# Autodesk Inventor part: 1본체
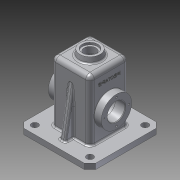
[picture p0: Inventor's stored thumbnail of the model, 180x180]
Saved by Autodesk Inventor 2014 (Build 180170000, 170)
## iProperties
Created: 2016-02
Part Number: 1본체
Material: 알루미늄 6061
Document SubType Name: Modeling
Designer: SEC
Density: 2.71 g/cm^3
Appearance: 알루미늄 - 평지
Mass: 923.206 g
Surface Area: 1053.79 cm^2
Volume: 340.666 cm^3
Author: SEC
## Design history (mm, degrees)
sketch "스케치1"
  geometry: L1 (-35, 60)-(35, 60); L2 (35, 60)-(35, -60); L3 (35, -60)-(-35, -60); L4 (-35, -60)-(-35, 60); L5 (-35, 60)-(35, -60); L6 (35, 60)-(-35, -60); 1 further point
  constraints: 12 end point, 2 midpoint, 2 parallel, 1 horizontal, 1 perpendicular
  dimensions: "d0" = 70 distance of L1.start L1.end; "d1" = 120 distance of L1.end L2.end
extrude "돌출1" new body sketch "스케치1" stored distance "d2" = 70; taper "d3" = 0 deg
sketch "스케치2"
  geometry: L1 (-35, -60)-(35, -60) reference; C1 r 27.5 at (0, -5); 1 further point
  constraints: 1 centre point, 1 vertical alignment
  dimensions: "d4" = 55 diameter of C1; "d5" = 55 distance from line of C1.centre L1
extrude "돌출2" join sketch "스케치2" distance "d6" = 13; taper "d7" = 0 deg
sketch "스케치3"
  geometry: L1 (22.5, 48)-(-32.5, 48) reference; L2 (22.5, -48)-(-32.5, -48) reference; L3 (-60, 35)-(-60, -35) reference; L4 (60, -35)-(60, 35) reference; L5 (-5, 48)-(-5, -48); L6 (55, 30)-(55, -30); L7 (60, 35)-(-60, 35) reference; L8 (-60, -35)-(60, -35) reference; L9 (-60, 30)-(-60, -30); L10 (55, 30)-(-60, 30); L11 (55, -30)-(-60, -30); 1 further point
  constraints: 10 end point, 2 midpoint, 2 point on line, 1 collinear, 1 parallel, 1 perpendicular
  dimensions: "d13" = 5 distance between parallel lines of L6 L4; "d35" = 5 distance between parallel lines of L7 L10; "d36" = 5 distance between parallel lines of L8 L11
extrude "돌출3" cut sketch "스케치3" stored distance "d19" = 60; taper "d20" = 0 deg
fillet "모깎기3" dims "d23" = 8
fillet "모깎기4" dims "d24" = 8
sketch "스케치4"
  geometry: L1 (22.5, 48)-(-32.5, 48) reference; L2 (22.5, -48)-(-32.5, -48) reference; L3 (-60, 27)-(-60, 35) reference; L4 (-60, -30)-(-60, 30) reference; L5 (-60, -35)-(-60, -27) reference; L6 (-5, 48)-(-5, -48); L7 (-60, 30)-(55, 30) reference; L8 (22.5, 30)-(15.5, 23); L9 (15.5, 23)-(12.5, 23); L10 (12.5, 23)-(12.5, 30); L11 (22.5, 30)-(12.5, 30); 1 further point
  constraints: 10 end point, 2 midpoint, 2 point on line, 1 collinear, 1 parallel, 1 perpendicular
  dimensions: "d37" = 55 diameter of L8.start L6; "d38" = 7 distance from line of L7 L8.end; "d39" = 135 deg angle of L7 L8; "d40" = 35 diameter of L9.end L6
revolve "회전1" sketch "스케치4" stored, may be unused: angle "d41" = 90 deg
hole "구멍1" diameter "d27" = 32; stored, may be unused: countersink angle "d31" = 90 deg, drill point angle "d33" = 118 deg; dims "d25" = 10, "d26" = 10, "d28" = 6, "d29" = 4, "d30" = 2, "d32" = 8
node "작업 평면1"
sketch "스케치5"
  geometry: C1 r 20 at (27, 27); 1 further point
  constraints: 1 centre point, 1 coincident
  dimensions: "d43" = 40 diameter of C1
extrude "돌출4" join sketch "스케치5" stored distance "d44" = 60; taper "d45" = 0 deg
sketch "스케치6"
  geometry: L1 (60, 27)-(60, -27) reference; L2 (70, 20)-(60, 20) reference; L3 (70, -20)-(60, -20) reference; L4 (70, 0)-(0, 0); L5 (60, 20)-(70, 20); L6 (60, 20)-(70, 18.237); L7 (70, 20)-(70, 18.237); L8 (0.22, 35)-(52, 35) reference
  constraints: 8 end point, 1 collinear, 1 parallel, 1 perpendicular
  dimensions: "d46" = 10 deg angle of L8 L6
revolve "회전2" sketch "스케치6" stored, may be unused: angle "d47" = 90 deg
hole "구멍2" diameter "d50" = 21; stored, may be unused: countersink angle "d54" = 90 deg, drill point angle "d56" = 118 deg; dims "d48" = 10, "d49" = 10, "d51" = 6, "d52" = 28, "d53" = 4, "d55" = 8
sketch "스케치7" dims "d57" = 45
  geometry: L1 (0, 0)-(0, 22.5); C1 r 27.5 at (0, 0) reference; 2 further points
  constraints: 2 coincident, 2 end point, 1 vertical, 1 vertical alignment, 2 other
hole "구멍3" sketch "스케치7" at (0, 22.5) diameter "d58" = 3.242; stored, may be unused: countersink angle "d62" = 90 deg, drill point angle "d64" = 118 deg; dims "d59" = 8, "d60" = 28, "d61" = 4, "d63" = 10
sketch "스케치8"
  geometry: L1 (62, -8)-(62, -62) reference; L2 (0, 0)-(54, 0) reference; L3 (-8, -8)-(-8, -62) reference; L4 (54, -70)-(0, -70) reference; L5 (-38, -100)-(92, -100); L6 (92, -100)-(92, 30); L7 (92, 30)-(-38, 30); L8 (-38, 30)-(-38, -100); L9 (-38, -100)-(92, 30); L10 (92, -100)-(-38, 30); A1 r 8 centre (54, -62) between (54, -70) and (62, -62) reference; A2 r 8 centre (54, -8) between (62, -8) and (54, 0) reference; A3 r 8 centre (0, -8) between (0, 0) and (-8, -8) reference; A4 r 8 centre (0, -62) between (-8, -62) and (0, -70) reference; 1 further point
  constraints: 12 end point, 2 midpoint, 2 parallel, 1 horizontal, 1 perpendicular
  dimensions: "d68" = 130 distance of L6.end L7.end; "d69" = 130 distance of L7.end L5.start
extrude "돌출5" join sketch "스케치8" distance "d70" = 10; taper "d71" = 0 deg
chamfer "모따기1" distance "d72" = 10; stored, may be unused: second distance "d73" = 2, angle "d74" = 45 deg
hole "구멍4" diameter "d77" = 12; stored, may be unused: countersink angle "d81" = 90 deg, drill point angle "d83" = 118 deg; dims "d75" = 15, "d76" = 15, "d78" = 8, "d79" = 28, "d80" = 4, "d82" = 10
sketch "스케치9"
  geometry: L1 (65, -50)-(65, -60) reference; L2 (35, 52)-(35, -50) reference; L3 (-55, -60)-(55, -60) reference; L4 (65, -60)-(55, -60) reference; L5 (55, -50)-(-55, -50) reference; L6 (55, -50)-(65, -50) reference; L7 (50, -50)-(35, 35.069); 1 further point
  constraints: 2 end point, 2 point on line
  dimensions: "d90" = 10 deg angle of L1 L7; "d91" = 15 horizontal distance of L1.end L7.start
feature "리브1" sketch "스케치9" dims "d92" = 1, "d93" = 10, "d94" = 0, "d95" = 0, "d96" = 1, "d97" = 1
fillet "모깎기6" dims "d98" = 3
fillet "모깎기7" dims "d99" = 3
fillet "모깎기8" dims "d100" = 3
fillet "모깎기9" dims "d101" = 3
fillet "모깎기10" dims "d102" = 3
fillet "모깎기11" dims "d103" = 3
fillet "모깎기12" dims "d104" = 0.5
fillet "모깎기13" dims "d105" = 0.5
chamfer "모따기2" distance "d106" = 1; stored, may be unused: second distance "d107" = 2, angle "d108" = 45 deg
node "작업 평면2"
sketch "스케치10"
  geometry: L1 (18.237, 70)-(-18.237, 70) reference; L2 (35, -47)-(35, 52) reference; 2 further points
  constraints: 1 other
  dimensions: "d110" = 30 distance from line of point (0, 40) L1; "d111" = 35 distance from line of point (0, 40) L2
feature "엠보싱1" sketch "스케치10" dims "d112" = 0.5, "d113" = 0
fillet "모깎기14" dims "d114" = 3
fillet "모깎기15" dims "d115" = 3
node "솔리드1"
mirror "대칭1"
mirror "대칭2"
pattern_circular "원형 패턴1" dims angle "d66" = 360 deg
mirror "대칭3"
pattern_linear "직사각형 패턴1" dims "d86" = 100
mirror "대칭4"
